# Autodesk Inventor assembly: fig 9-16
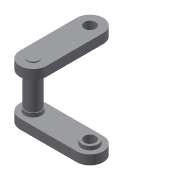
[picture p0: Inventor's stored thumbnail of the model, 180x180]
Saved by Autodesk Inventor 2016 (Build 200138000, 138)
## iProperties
Shininess: 64.0
Length Units: 11269
Angle Units: 11279
Time Units: 11290
Mass Units: 11283
Length Display Precision: 3
Angle Display Precision: 2
Created: 2002-01
Part Number: fig 9-16
Document SubType Name: Assembly
Designer: ***
Density: 0.0
Volumn: 0.0
Area: 0.0
PropertySet Name: Model Information
Control State: 0
Master: False
Checked Out: False
Author: ***
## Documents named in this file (3)
- D:\KAVITA\Autodesk Inventor_ 2016 Project_Kavita\Inventor_Part Files\Inventor_2016_Part\c09_Inv_2016\c09_inv_2016_prt\fig 9-16.iam
- D:\KAVITA\Autodesk Inventor_ 2016 Project_Kavita\Inventor_Part Files\Inventor_2016_Part\c09_Inv_2016\c09_inv_2016_prt\Part5.ipt
- D:\KAVITA\Autodesk Inventor_ 2016 Project_Kavita\Inventor_Part Files\Inventor_2016_Part\c09_Inv_2016\c09_inv_2016_prt\Part6.ipt
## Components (3 placed, 2 different names)
1. Part5:1 — Insert:1, Angle:1
2. Part6:1 — Insert:1, Insert:2
3. Part5:2 — Insert:2, Angle:1
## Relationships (3: Insert 2, Angle 1)
- Insert:1: Part5:1 ↔ Part6:1
- Insert:2: Part6:1 ↔ Part5:2
- Angle:1: Part5:1 ↔ Part5:2
